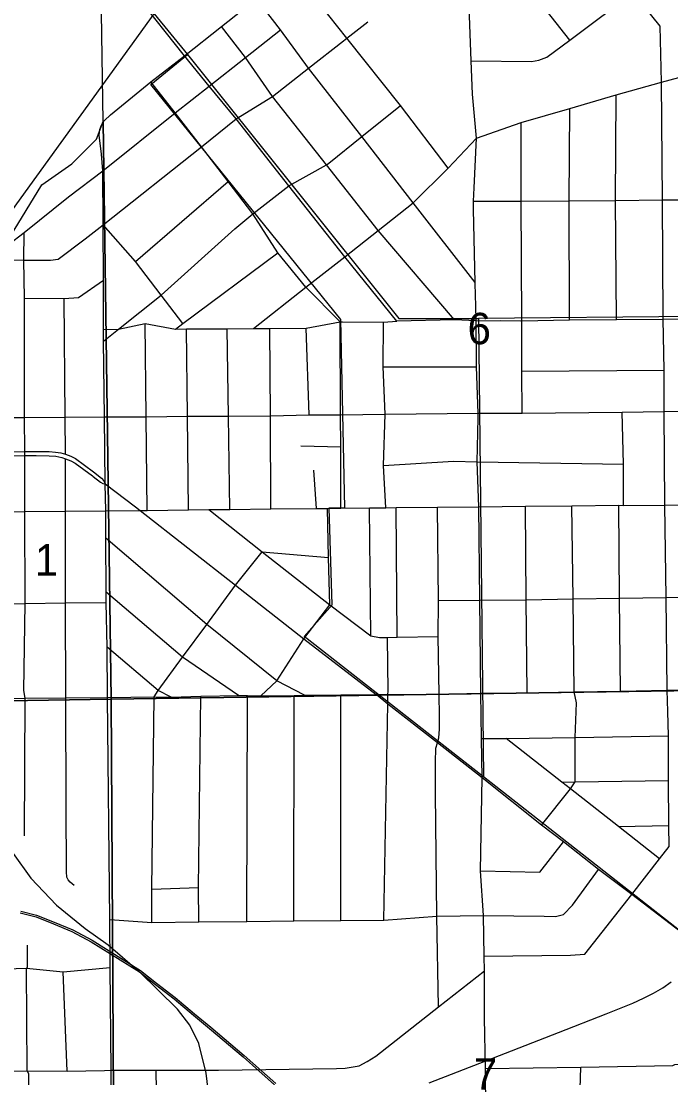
# Model space of a CAD drawing. Extents: x 0 to 40.2, y 0 to 22.
# Drawn here: x 3.009 to 3.875, y 18.165 to 19.573 of the extents above; entities that cross this region are included whole.
import ezdxf

# ---------------------------------------------------------------- set-up
doc = ezdxf.new("R2010")
doc.units = 0
for name, color, linetype in [('GM_X_City_Street', 7, 'Continuous'), ('GM_X_Corporation', 7, 'Continuous'), ('GM_X_Major_Lake', 7, 'Continuous'), ('GM_X_Major_Lake_Text', 7, 'Continuous'), ('GM_X_Major_River', 7, 'Continuous'), ('GM_X_Unincorporated_Location', 7, 'Continuous')]:
    doc.layers.add(name, color=color, linetype=linetype)

msp = doc.modelspace()

# ---------------------------------------------------------------- linework, layer by layer
at = {"layer": 'GM_X_Corporation'}
for points in [[(3.1145, 19.6715), (4.1148, 19.68), (4.119, 18.6842), (3.1284, 18.6693), (3.1181, 19.4397)], [(2.9569, 19.2264), (3.0363, 19.3549), (3.0761, 19.383), (3.1089, 19.4158), (3.1181, 19.4397), (3.1284, 18.6693), (2.9612, 18.6668)], [(4.119, 18.6842), (4.1323, 17.6892), (3.1342, 17.6788), (3.1284, 18.6693)], [(3.1284, 18.6693), (3.1342, 17.6788), (2.961, 17.6763), (2.9607, 17.9101), (2.9612, 18.6668)]]:
    msp.add_lwpolyline(points, close=True, dxfattribs=at)
at = {"layer": 'GM_X_Major_Lake'}
for p, q in [((3.0185, 18.9943), (3.0286, 18.9942)), ((3.1208, 18.9566), (3.1609, 18.9258))]:
    msp.add_line(p, q, dxfattribs=at)
for points in [[(2.3915, 19.0581), (2.4021, 19.0551), (2.4148, 19.0532), (2.4212, 19.0529), (2.4727, 19.046), (2.629, 19.0257), (2.789, 19.0047), (2.8236, 18.9995), (2.8488, 18.9955), (2.8585, 18.9944), (2.8681, 18.9937), (2.8877, 18.9931), (2.9585, 18.9938), (3.0135, 18.9943), (3.0185, 18.9943)], [(2.9585, 18.9992), (3.0134, 18.9997), (3.0458, 18.9995), (3.0542, 18.9988), (3.0616, 18.9977), (3.0678, 18.996), (3.0749, 18.9932), (3.081, 18.9902), (3.1052, 18.9726), (3.1159, 18.964), (3.1187, 18.9605), (3.1208, 18.9566)], [(3.0286, 18.9942), (3.0458, 18.994), (3.0546, 18.9932), (3.0627, 18.9914), (3.0679, 18.9899)], [(3.0679, 18.9899), (3.0747, 18.9872), (3.0806, 18.9839), (3.1035, 18.967)], [(3.1035, 18.967), (3.1044, 18.9664), (3.1142, 18.9587), (3.1175, 18.9571), (3.1208, 18.9566)], [(3.1266, 18.3756), (3.1238, 18.6719), (3.1231, 18.739), (3.122, 18.7983), (3.122, 18.812), (3.1215, 18.884), (3.1215, 18.9207), (3.1208, 18.9566)], [(3.1609, 18.9258), (3.1673, 18.9209), (3.2944, 18.8214), (3.3856, 18.7498), (3.4818, 18.6756)], [(3.6214, 18.6773), (3.6834, 18.678), (3.746, 18.6793), (3.8079, 18.6803), (3.8699, 18.6813)], [(3.8699, 18.6813), (3.9326, 18.6813), (3.9948, 18.6817), (4.0572, 18.6825), (4.117, 18.6834), (4.119, 18.6834)], [(3.4818, 18.6756), (3.4974, 18.6756), (3.5659, 18.6763), (3.6214, 18.6773)], [(3.6234, 18.5645), (3.5636, 18.6114), (3.4975, 18.6626), (3.4818, 18.6756)], [(3.9458, 18.3151), (3.8229, 18.4092), (3.7783, 18.4425), (3.7316, 18.4792), (3.7026, 18.5017), (3.6234, 18.5645)], [(3.1197, 18.1746), (3.1287, 18.1748), (3.1274, 18.3119), (3.1266, 18.3756)], [(2.9034, 18.1683), (2.9114, 18.1731), (2.9176, 18.1742), (2.961, 18.1736), (3.0165, 18.1742), (3.0698, 18.1738), (3.1197, 18.1746)]]:
    msp.add_lwpolyline(points, dxfattribs=at)
at = {"layer": 'GM_X_Major_Lake_Text'}
for p in [(3.5778, 19.3775), (3.6125, 19.3509)]:
    msp.add_line(p, (3.6156, 19.4174), dxfattribs=at)
for points in [[(3.2263, 19.5272), (3.2756, 19.5661), (3.3222, 19.6035), (3.3709, 19.6418), (3.4643, 19.7159), (3.5094, 19.7519), (3.5585, 19.7904), (3.5961, 19.8213), (3.6356, 19.8523), (3.6736, 19.8832), (3.7111, 19.9151), (3.75, 19.9456)], [(3.2263, 19.5272), (3.1626, 19.6074), (3.0718, 19.7224), (3.0058, 19.8009), (2.9768, 19.8371), (2.938, 19.8826), (2.9218, 19.9099)], [(3.6156, 19.4174), (3.6753, 19.4382), (3.7403, 19.4567), (3.8018, 19.4749), (3.8624, 19.4921), (3.9252, 19.5089), (3.9827, 19.5231), (4.0225, 19.5337), (4.149, 19.5748), (4.191, 19.5885), (4.3232, 19.6297), (4.3386, 19.6349), (4.3427, 19.6363), (4.3493, 19.6382), (4.4443, 19.6659), (4.4771, 19.6761), (4.505, 19.6806), (4.5246, 19.6809), (4.5781, 19.6818), (4.6407, 19.6829), (4.8325, 19.6861), (5.1048, 19.6908), (5.1167, 19.691)], [(3.5778, 19.3775), (3.5142, 19.4608), (3.4429, 19.5506), (3.3709, 19.6418)], [(3.1196, 19.4408), (3.1275, 19.4483), (3.1814, 19.4923), (3.2263, 19.5272)], [(3.5097, 19.1732), (3.4401, 19.2593), (3.3653, 19.3539), (3.2954, 19.443), (3.2593, 19.4866), (3.2263, 19.5272)], [(3.1208, 18.9566), (3.1196, 19.0457), (3.1183, 19.1466), (3.1183, 19.1624), (3.1182, 19.2279), (3.118, 19.3017), (3.1175, 19.3738), (3.1156, 19.3958), (3.1126, 19.4212), (3.1135, 19.4288), (3.1155, 19.4348), (3.1182, 19.4394), (3.1196, 19.4408)], [(2.9721, 19.2597), (2.9917, 19.2756), (3.0125, 19.2917), (3.0717, 19.3391), (3.1175, 19.3738)], [(3.6145, 19.2069), (3.6141, 19.2248), (3.6119, 19.3223), (3.6116, 19.3331), (3.6125, 19.3509)], [(3.6152, 19.1738), (3.6148, 19.1946), (3.6145, 19.2069)], [(3.6152, 19.1738), (3.5864, 19.1751), (3.5097, 19.1732)], [(3.6152, 19.1738), (3.648, 19.1742), (3.675, 19.1739)], [(3.6178, 19.0446), (3.6179, 19.0505), (3.6158, 19.1123), (3.6152, 19.1738)], [(3.675, 19.1739), (3.676, 19.1739), (3.7395, 19.1751), (3.8025, 19.1755), (3.8644, 19.176), (3.9271, 19.1767), (3.988, 19.1778), (4.0501, 19.1787), (4.1114, 19.1794), (4.1746, 19.1803), (4.2286, 19.1817), (4.2914, 19.1812), (4.3483, 19.1821), (4.3649, 19.1816), (4.4183, 19.1836)], [(3.6214, 18.6773), (3.6202, 18.8015), (3.6188, 18.926), (3.6165, 18.9859), (3.6178, 19.0446)], [(3.6234, 18.5645), (3.6222, 18.6169), (3.6214, 18.6773)], [(3.7652, 17.4109), (3.7581, 17.4279), (3.7312, 17.4826), (3.7273, 17.4904), (3.712, 17.5227), (3.651, 17.6432), (3.6334, 17.6829), (3.6324, 17.7394), (3.6321, 17.806), (3.6294, 17.9688), (3.6293, 18.0271), (3.6287, 18.0607), (3.6283, 18.1199), (3.6278, 18.1771), (3.6262, 18.2446), (3.6262, 18.3075), (3.6258, 18.3267), (3.6252, 18.3809), (3.6209, 18.4405), (3.6234, 18.5645)]]:
    msp.add_lwpolyline(points, dxfattribs=at)
at = {"layer": 'GM_X_Major_River'}
for p, q in [((3.1859, 19.5828), (3.2304, 19.5288)), ((4.122, 19.182), (3.6184, 19.1768)), ((3.6184, 19.1768), (3.625, 18.5659)), ((3.921, 18.3338), (3.625, 18.5659))]:
    msp.add_line(p, q, dxfattribs=at)
for points in [[(2.9186, 18.5659), (2.885, 18.6143), (2.8725, 18.6374), (2.8581, 18.6687), (2.847, 18.6975), (2.8307, 18.7539), (2.8162, 18.8251), (2.809, 18.8756), (2.8056, 18.9112), (2.8052, 18.9415), (2.8076, 18.993), (2.8225, 19.0604), (2.8454, 19.1146), (2.8753, 19.1549), (2.9643, 19.2767), (3.1859, 19.5828)], [(3.625, 18.5659), (3.3859, 18.7532), (3.4232, 18.7951), (3.4194, 18.9245), (3.44, 18.9245), (3.4348, 19.1755), (3.1815, 19.4889), (3.2304, 19.5288)], [(3.2304, 19.5288), (3.512, 19.1768), (3.6184, 19.1768)], [(2.9186, 18.5659), (2.9768, 18.492), (2.9977, 18.4636), (3.0216, 18.4308), (3.0559, 18.395), (3.094, 18.3636), (3.1246, 18.342), (3.166, 18.3064)], [(3.0073, 18.3847), (3.0284, 18.3792), (3.0515, 18.3699), (3.0763, 18.3597), (3.1019, 18.3461), (3.1663, 18.3059), (3.1877, 18.2892), (3.2125, 18.2699), (3.2382, 18.2481), (3.2598, 18.2304), (3.3044, 18.1928), (3.3464, 18.1555)], [(3.008, 18.387), (3.0291, 18.3814), (3.0524, 18.372), (3.0773, 18.3618), (3.1031, 18.3481), (3.1676, 18.3078), (3.1891, 18.291), (3.2139, 18.2717), (3.2397, 18.2498), (3.2613, 18.2322), (3.306, 18.1946), (3.348, 18.1572)], [(3.1789, 17.9668), (3.2021, 17.9894), (3.2209, 18.0144), (3.2341, 18.039), (3.2469, 18.0673), (3.2551, 18.1039), (3.2589, 18.1412), (3.2551, 18.1711), (3.2454, 18.2106), (3.2333, 18.2347), (3.2171, 18.2562), (3.166, 18.3064)], [(3.5526, 18.1579), (3.6281, 18.1875), (3.725, 18.2253), (3.7885, 18.2499), (3.8242, 18.2641), (3.8386, 18.2707), (3.8517, 18.2774), (3.8641, 18.2848), (3.8754, 18.2927)]]:
    msp.add_lwpolyline(points, dxfattribs=at)
at = {"layer": 'GM_X_Unincorporated_Location'}
for p, q in [((3.1609, 19.2529), (3.2847, 19.3596)), ((3.3926, 19.0484), (3.3885, 19.1639)), ((3.4912, 19.1126), (3.6158, 19.1123)), ((3.6763, 19.1068), (3.8659, 19.108)), ((3.3816, 19.0073), (3.4349, 19.0057)), ((3.4022, 18.9238), (3.3988, 18.9748)), ((3.4746, 18.7538), (3.473, 18.9247)), ((3.5101, 18.7519), (3.5088, 18.9248)), ((3.3095, 18.3732), (3.3102, 18.6743)), ((3.3721, 18.3738), (3.3728, 18.6745)), ((3.4348, 18.3744), (3.435, 18.6752)), ((3.8052, 18.4999), (3.872, 18.5011)), ((3.1826, 18.416), (3.2451, 18.4186)), ((3.0698, 18.1738), (3.0648, 18.3062))]:
    msp.add_line(p, q, dxfattribs=at)
for points in [[(3.8624, 19.4921), (3.8604, 19.5666), (3.8308, 19.6041), (3.8252, 19.6111), (3.7253, 19.7376), (3.6356, 19.8523)], [(3.7402, 19.548), (3.6423, 19.6723), (3.5585, 19.7904)], [(3.6156, 19.4174), (3.6104, 19.4758), (3.6088, 19.5203), (3.6042, 19.6412), (3.6036, 19.6419), (3.6009, 19.6449), (3.5789, 19.6706)], [(3.6088, 19.5203), (3.6892, 19.5194), (3.6987, 19.5212), (3.7097, 19.5253), (3.7402, 19.548), (3.783, 19.5798), (3.8252, 19.6111), (3.8614, 19.638), (3.9629, 19.6495)], [(3.6141, 19.2248), (3.5314, 19.331), (3.4626, 19.4194), (3.3917, 19.5104), (3.3543, 19.5617), (3.3222, 19.6035)], [(2.9586, 19.2486), (2.974, 19.2556), (3.0123, 19.2547), (3.0477, 19.2547), (3.0577, 19.2562), (3.094, 19.2833), (3.118, 19.3017), (3.2491, 19.4057), (3.2954, 19.443), (3.3436, 19.4726), (3.3917, 19.5104), (3.4384, 19.547), (3.4429, 19.5506), (3.4706, 19.5724)], [(3.5864, 19.1751), (3.4846, 19.2942), (3.4155, 19.3816), (3.3436, 19.4726), (3.3075, 19.5247), (3.2756, 19.5661)], [(3.2593, 19.4866), (3.3075, 19.5247), (3.3543, 19.5617)], [(3.1175, 19.3738), (3.214, 19.4512), (3.2593, 19.4866)], [(3.4348, 18.9241), (3.4349, 19.0057), (3.4343, 19.0486), (3.4338, 19.1724), (3.3882, 19.2185), (3.3509, 19.2645), (3.3175, 19.3164), (3.2847, 19.3596), (3.2491, 19.4057), (3.214, 19.4512), (3.1814, 19.4923)], [(3.8699, 18.6813), (3.8687, 18.8049), (3.8668, 18.928), (3.866, 19.0528), (3.8659, 19.108), (3.8644, 19.176), (3.8636, 19.3353), (3.8624, 19.4921)], [(3.8025, 19.1755), (3.801, 19.3344), (3.8018, 19.4749)], [(3.4187, 19.3841), (3.4626, 19.4194), (3.5142, 19.4608)], [(3.7395, 19.1751), (3.7391, 19.3336), (3.7403, 19.4567)], [(3.6767, 19.0509), (3.6763, 19.1068), (3.676, 19.1739), (3.6753, 19.3332), (3.6753, 19.4382)], [(3.3653, 19.3539), (3.4155, 19.3816), (3.4187, 19.3841)], [(3.3182, 19.1635), (3.3882, 19.2185), (3.4401, 19.2593), (3.4846, 19.2942), (3.5314, 19.331), (3.5778, 19.3775)], [(3.1183, 19.1466), (3.1383, 19.1625), (3.1953, 19.2081), (3.2934, 19.2964), (3.3175, 19.3164), (3.3653, 19.3539)], [(3.6116, 19.3331), (3.6753, 19.3332), (3.7391, 19.3336), (3.801, 19.3344), (3.8636, 19.3353), (3.9248, 19.3353), (3.9878, 19.3361), (4.0495, 19.3365), (4.1089, 19.3371), (4.1457, 19.3375), (4.1585, 19.338), (4.1997, 19.338), (4.2433, 19.3344), (4.3049, 19.3348), (4.3597, 19.3351), (4.3645, 19.3351), (4.4203, 19.3398), (4.4638, 19.3426), (4.4705, 19.3397)], [(3.2243, 19.1704), (3.1953, 19.2081), (3.1609, 19.2529), (3.118, 19.3017)], [(3.0129, 18.4873), (3.0139, 18.6708), (3.0122, 18.6808), (3.014, 18.7968), (3.0134, 18.9196), (3.0135, 18.9943), (3.0134, 18.9997), (3.0131, 19.045), (3.0132, 19.204), (3.0123, 19.2547), (3.0125, 19.2917)], [(3.2142, 19.1629), (3.2243, 19.1704), (3.3509, 19.2645)], [(3.0132, 19.204), (3.0658, 19.2034), (3.0851, 19.205), (3.1182, 19.2279)], [(3.0678, 18.996), (3.0673, 19.0455), (3.0658, 19.2034)], [(3.1183, 19.1624), (3.1383, 19.1625), (3.1741, 19.1704), (3.2142, 19.1629), (3.229, 19.163), (3.2833, 19.1633), (3.3182, 19.1635), (3.3403, 19.1636), (3.3885, 19.1639), (3.4338, 19.1724), (3.4369, 19.1724)], [(3.4369, 19.1724), (3.4919, 19.1721), (3.5097, 19.1732)], [(3.4949, 18.9247), (3.4915, 18.9809), (3.4939, 19.0494), (3.4912, 19.1126), (3.4919, 19.1721)], [(3.1764, 18.921), (3.1751, 19.046), (3.1741, 19.1704)], [(3.2315, 18.9218), (3.2302, 19.0466), (3.229, 19.163)], [(3.2866, 18.9223), (3.2851, 19.0466), (3.2833, 19.1633)], [(3.3416, 18.9232), (3.3409, 19.0473), (3.3403, 19.1636)], [(2.8306, 19.0445), (2.9582, 19.045), (3.0131, 19.045), (3.0673, 19.0455), (3.1196, 19.0457), (3.1751, 19.046), (3.2302, 19.0466), (3.2851, 19.0466), (3.3409, 19.0473), (3.3926, 19.0484), (3.4343, 19.0486), (3.4939, 19.0494), (3.6179, 19.0505), (3.6767, 19.0509), (3.8101, 19.0522), (3.866, 19.0528), (3.929, 19.0534), (3.991, 19.0543), (4.0538, 19.0446), (4.1776, 19.0474), (4.2923, 19.0576), (4.4726, 19.0593), (4.5078, 19.0596)], [(3.8119, 18.9278), (3.8119, 18.9826), (3.8101, 19.0522)], [(3.0792, 18.4209), (3.074, 18.4255), (3.0711, 18.4287), (3.0696, 18.432), (3.069, 18.4393), (3.0688, 18.5267), (3.0681, 18.6714), (3.0678, 18.7977), (3.0676, 18.92), (3.0679, 18.9899)], [(3.4915, 18.9809), (3.5849, 18.9869), (3.6165, 18.9859), (3.8119, 18.9826)], [(2.8172, 18.9177), (2.9587, 18.919), (3.0134, 18.9196), (3.0676, 18.92), (3.1215, 18.9207)], [(3.1215, 18.9207), (3.1673, 18.9209), (3.1764, 18.921), (3.2315, 18.9218), (3.2589, 18.9221), (3.2866, 18.9223), (3.3416, 18.9232), (3.4022, 18.9238), (3.417, 18.9238), (3.4348, 18.9241), (3.473, 18.9247), (3.4949, 18.9247), (3.5088, 18.9248), (3.5636, 18.9253), (3.6188, 18.926), (3.6811, 18.9266), (3.743, 18.9274), (3.8053, 18.928), (3.8119, 18.9278), (3.8668, 18.928), (3.9299, 18.9287)], [(3.2589, 18.9221), (3.3298, 18.866), (3.4202, 18.7953), (3.4746, 18.7538), (3.4865, 18.7516), (3.4972, 18.7518), (3.5101, 18.7519), (3.5646, 18.753)], [(3.3283, 18.674), (3.3495, 18.6939), (3.3856, 18.7498), (3.4202, 18.7953), (3.4185, 18.8585), (3.417, 18.9238)], [(3.5649, 18.2594), (3.5628, 18.38), (3.5609, 18.5441), (3.5611, 18.5853), (3.5617, 18.6042), (3.5636, 18.6114), (3.5656, 18.6178), (3.5663, 18.6294), (3.5662, 18.6467), (3.5659, 18.6763), (3.5646, 18.753), (3.5649, 18.8012), (3.5636, 18.9253)], [(3.6834, 18.678), (3.682, 18.8018), (3.6811, 18.9266)], [(3.7026, 18.5017), (3.7409, 18.5501), (3.7473, 18.5591), (3.7471, 18.6183), (3.749, 18.6645), (3.746, 18.6793), (3.7447, 18.803), (3.743, 18.9274)], [(3.8079, 18.6803), (3.8064, 18.804), (3.8053, 18.928)], [(3.3864, 18.675), (3.3495, 18.6939), (3.2561, 18.7692), (3.1215, 18.884)], [(3.186, 18.6728), (3.1912, 18.6809), (3.2239, 18.7254), (3.2561, 18.7692), (3.2944, 18.8214), (3.3298, 18.866), (3.4185, 18.8585)], [(3.2982, 18.6742), (3.2239, 18.7254), (3.122, 18.812)], [(3.5649, 18.8012), (3.6202, 18.8015), (3.682, 18.8018), (3.7447, 18.803), (3.8064, 18.804), (3.8687, 18.8049), (3.9317, 18.8053), (3.9936, 18.8054), (3.9992, 18.8046), (4.056, 18.805), (4.1159, 18.8055)], [(2.8269, 18.7949), (2.9073, 18.7954), (2.9587, 18.7966), (3.014, 18.7968), (3.0678, 18.7977), (3.122, 18.7983)], [(3.4922, 18.375), (3.4975, 18.6626), (3.4974, 18.6756), (3.498, 18.6801), (3.4972, 18.7518)], [(3.2088, 18.6723), (3.1912, 18.6809), (3.1231, 18.739)], [(3.8728, 18.4732), (3.872, 18.5011), (3.8716, 18.5609), (3.8717, 18.6206), (3.8707, 18.6532), (3.8699, 18.6813)], [(2.8634, 18.6679), (2.9082, 18.6693), (2.9592, 18.6701), (3.0139, 18.6708), (3.0681, 18.6714), (3.1238, 18.6719), (3.186, 18.6728), (3.2088, 18.6723), (3.2482, 18.6733), (3.2982, 18.6742), (3.3102, 18.6743), (3.3283, 18.674), (3.3728, 18.6745), (3.3864, 18.675), (3.435, 18.6752), (3.4818, 18.6756)], [(3.183, 18.3719), (3.1826, 18.416), (3.186, 18.6728)], [(3.2456, 18.3725), (3.2451, 18.4186), (3.2482, 18.6733)], [(3.6222, 18.6169), (3.6554, 18.6171), (3.7471, 18.6183), (3.8717, 18.6206)], [(3.8599, 18.4566), (3.8052, 18.4999), (3.7409, 18.5501), (3.7297, 18.559), (3.6554, 18.6171)], [(3.7297, 18.559), (3.7473, 18.5591), (3.8716, 18.5609)], [(3.6209, 18.4405), (3.7003, 18.439), (3.7316, 18.4792)], [(3.6258, 18.3267), (3.7411, 18.328), (3.7602, 18.3296), (3.8229, 18.4092), (3.8599, 18.4566), (3.8728, 18.4732)], [(3.1266, 18.3756), (3.183, 18.3719), (3.2456, 18.3725), (3.3095, 18.3732), (3.3721, 18.3738), (3.4348, 18.3744), (3.4922, 18.375), (3.5628, 18.38), (3.6252, 18.3809), (3.7058, 18.38), (3.721, 18.3797), (3.7317, 18.3826), (3.7437, 18.3949), (3.7783, 18.4425)], [(3.0163, 17.6767), (3.0163, 17.684), (3.0182, 17.694), (3.0193, 17.7028), (3.0197, 17.7128), (3.0195, 17.7234), (3.0178, 17.7939), (3.019, 17.8516), (3.0185, 17.8887), (3.0182, 17.9413), (3.0183, 18.0077), (3.0184, 18.0924), (3.0188, 18.1699), (3.0165, 18.1742), (3.0159, 18.311), (3.0172, 18.3124), (3.0168, 18.3417)], [(2.906, 18.3101), (2.9602, 18.3093), (3.0159, 18.311), (3.0648, 18.3062), (3.1274, 18.3119)], [(3.4591, 18.1807), (3.4699, 18.1865), (3.4816, 18.1936), (3.5649, 18.2594), (3.6262, 18.3075)], [(3.1287, 18.1748), (3.1887, 18.1748), (3.2719, 18.1748), (3.4291, 18.1771), (3.4408, 18.1774), (3.4591, 18.1807)], [(3.1293, 18.0902), (3.1293, 18.0921), (3.1287, 18.1748)], [(3.171, 17.9829), (3.1773, 17.995), (3.1817, 18.0097), (3.1897, 18.0938), (3.1887, 18.1748)], [(3.6278, 18.1771), (3.7547, 18.1789), (3.8774, 18.181), (3.8801, 18.1825), (4.0126, 18.185), (4.065, 18.1851)], [(3.7559, 17.9133), (3.7553, 17.9698), (3.7549, 18.0006), (3.7547, 18.0222), (3.7541, 18.0282), (3.7535, 18.0616), (3.7531, 18.1218), (3.7547, 18.1789)]]:
    msp.add_lwpolyline(points, dxfattribs=at)

# ---------------------------------------------------------------- texts
at = {"layer": 'GM_X_City_Street'}
for s, p in [('6', (3.6038, 19.1426)), ('1', (3.0268, 18.8342)), ('7', (3.6122, 18.1489))]:
    msp.add_text(s, height=0.0419, rotation=0, dxfattribs=at).set_placement(p)

doc.saveas('drawing.dxf')
